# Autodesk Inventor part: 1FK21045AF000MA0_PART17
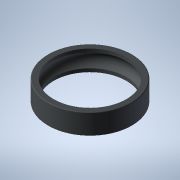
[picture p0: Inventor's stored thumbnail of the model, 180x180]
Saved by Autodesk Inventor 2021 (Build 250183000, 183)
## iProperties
Created: 2025-04
Part Number: 1FK21045AF000MA0_PART17
Material: Generic
Catalog Web Link: www.3dfindit.com
Description: -Servo synchronous motor
Document SubType Name: Modeling
Designer: psAdmin
Mass: 1.64389 g
Surface Area: 26.4305 cm^2
Volume: 1.64389 cm^3
Density: 1 g/cm^3
Appearance: PSOLRGB-212-217-219
Category: PARTsolutions
Title: 1FK21045AF000MA0_PART17
Author: Cadenas PARTsolutions
Comments: Servo synchronous motor
Sending System: PARTsolutions
Preprocessor: ST-DEVELOPER v19.3
PSOL_IDENT_0: {$CADENAS_DATA/23d-libs/siemens_ag/_cat_/8b/0a/1fk21045af000ma0.prj},216 {VTYP=3D},{NB=1FK21045AF000
PSOL_IDENT_1: MA0_PART17},{LINA=1FK21045AF000MA0_PART17},{NN=1FK21045AF000MA0_PART17},{NOPRJ=TRUE},{DATE=19.08.202
PSOL_IDENT_2: 5 14:00:48},{GEOMDATE=30.07.2025 02:00:28},{VERSION=},{LINEID=10},{WBVAR=},{WBNUMERIC=}  {NB=1FK2104
PSOL_IDENT_3: 5AF000MA0_PART17},{LINA=1FK21045AF000MA0_PART17},{KT=DUMMY},{PREVIEW=../../../_pool_/a9/69/p_d211_xx
PSOL_IDENT_4: _00818j.png},{DESCSHORT=SIMOTICS S-1FK2 HD, SINAMICS S210 3AC 400V-480V, 2.4 Nm, 3000 rpm},{DESCLONG=
PSOL_IDENT_5: SIMOTICS S-1FK2 HD servo motor M0=2.4 Nm; PN = 0.75 kW at nN=3000 rpm (380-480 V); PN = 0.375 kW at
PSOL_IDENT_6: nN=1500 rpm (200-240 V); degree of protection IP64; cylindrical shaft D19x40mm; absolute encoder 22-
PSOL_IDENT_7: bit + 12-bit multiturn (encoder AM22DQC); with OCC interface; plug size M17, rotatable; SIMOTICS S-1
PSOL_IDENT_8: FK2 servomotorfor a wide range of uses in industrial environments. SIMOTICS S‑1FK2 servomotors are c
PSOL_IDENT_9: ompact synchronous motors with a high dynamic performance that set themselves apart as a result of t
PSOL_IDENT_10: heir high power density, degree of protection and overload capability. The motors are available in t
PSOL_IDENT_11: wo variants: as High Dynamic variant (highest dynamic performance as a result of the low intrinsic m
PSOL_IDENT_12: oment of inertia for applications demanding a high dynamic performance with low moved masses) - and
PSOL_IDENT_13: as Compact variant (precise and stable closed-loop control for medium up to large moved masses as a
PSOL_IDENT_14: result of a medium intrinsic moment of inertia). SIMOTICSS‑1FK2 servomotors fully exploit their stre
PSOL_IDENT_15: ngths in a system with the SINAMICSS210 frequency converter and simple connection using the one cabl
PSOL_IDENT_16: e connection (OCC). Advantages include the short control and positioning times, fast and precise cor
PSOL_IDENT_17: rection of disturbing quantities as well as stable control with a high dynamic performance. The serv
PSOL_IDENT_18: o motors can be configured to address a wide range of requirements. For example with and without hol
PSOL_IDENT_19: ding brake, IP64 or IP65 degree of protection, singleturn or multiturn absolute encoders - to name j
PSOL_IDENT_20: ust a few. Further, the servomotors are available in different shaft heights extending from 20 to 10
PSOL_IDENT_21: 0. A shaft sealing ring is available to achieve an IP65 degree of protection and for subsequent moun
PSOL_IDENT_22: ting at the motor or as spare part. SIMOTICS - the optimum motor for each and every motion control a
PSOL_IDENT_23: pplication.},{INTNO=195125050112},{SUPPLIERALTNO=1FK2104-5AF00-0MA0},{MANUID=1FK21045AF000MA0},{MANU
PSOL_IDENT_24: NAME=Siemens},{MANUTYPEDESC=Synchronous motor 1FK2-HD 2.4 NM},{AAU732=SIMOTICS},{AAO057=S-1FK2},{AAU
PSOL_IDENT_25: 734=SIMOTICS S-1FK2 HD servo motor M0=2.4 Nm; PN = 0.75 kW at nN=3000 rpm (380-480 V); PN = 0.375 kW
PSOL_IDENT_26: at nN=1500 rpm (200-240 V); degree of protection IP64; cylindrical shaft D19x40mm; absolute encoder
PSOL_IDENT_27: 22-bit + 12-bit multiturn (encoder AM22DQC); with OCC interface; plug size M17, rotatable;},{AAW338=
PSOL_IDENT_28: Synchronous motor 1FK2-HD 2.4 NM},{AAO742=SIMOTICS},{AAO663=4042948692912},{NOCUPEROU=1},{PRICEQUANT
PSOL_IDENT_29: ITY=1},{QUANTITYMIN=1},{QUANTITYINT=1},{CTN=85015100},{COO=DE},{AAO676=1FK2104-5AF00-0MA0},{AAO677=S
PSOL_IDENT_30: iemens AG},{ORDERUNIT=C62},{CONTENTUNIT=C62}
NB: 1FK21045AF000MA0_PART17
NT: Servo synchronous motor
NBSYN: $MANUID._PART17
LINA: 1FK21045AF000MA0_PART17
CATALOG: SIEMENS
PREVIEW: ../../../_pool_/a9/69/p_d211_xx_00818j.png
DESCSHORT: SIMOTICS S-1FK2 HD, SINAMICS S210 3AC 400V-480V, 2.4 Nm, 3000 rpm
DESCLONG: SIMOTICS S-1FK2 HD servo motor M0=2.4 Nm; PN = 0.75 kW at nN=3000 rpm (380-480 V); PN = 0.375 kW at nN=1500 rpm (200-240 V); degree of protection IP64; cylindri
INTNO: 195125050112
SUPPLIERALTNO: 1FK2104-5AF00-0MA0
MANUID: 1FK21045AF000MA0
MANUNAME: Siemens
MANUTYPEDESC: Synchronous motor 1FK2-HD 2.4 NM
AAU732: SIMOTICS
AAO057: S-1FK2
AAU734: SIMOTICS S-1FK2 HD servo motor M0=2.4 Nm; PN = 0.75 kW at nN=3000 rpm (380-480 V); PN = 0.375 kW at nN=1500 rpm (200-240 V); degree of protection IP64; cylindri
AAW338: Synchronous motor 1FK2-HD 2.4 NM
AAO742: SIMOTICS
AAO663: 4042948692912.0
NOCUPEROU: 1
PRICEQUANTITY: 1
QUANTITYMIN: 1
QUANTITYINT: 1
CTN: 85015100
COO: DE
ARTICLENO: 1FK21045AF000MA0_PART17
BOMINFO: 1FK21045AF000MA0_PART17
CREATOR: CADENAS GmbH
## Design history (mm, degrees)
feature "2025_04_17_15_40_42_0766"
body "Solid1"
